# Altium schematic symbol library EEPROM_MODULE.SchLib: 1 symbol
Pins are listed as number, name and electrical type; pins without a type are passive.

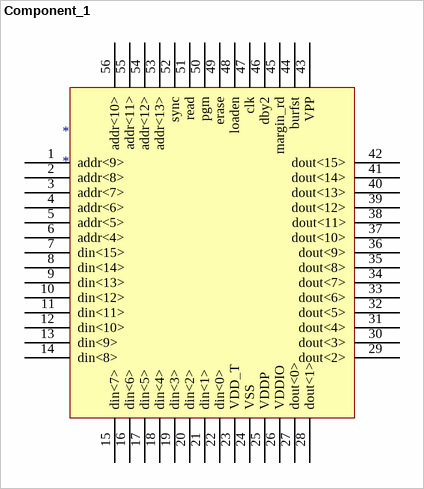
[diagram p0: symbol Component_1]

## Component_1
designator *
pins: 1 addr<9>, 2 addr<8>, 3 addr<7>, 4 addr<6>, 5 addr<5>, 6 addr<4>, 7 din<15>, 8 din<14>, 9 din<13>, 10 din<12>, 11 din<11>, 12 din<10>, 13 din<9>, 14 din<8>, 15 din<7>, 16 din<6>, 17 din<5>, 18 din<4>, 19 din<3>, 20 din<2>, 21 din<1>, 22 din<0>, 23 VDD_T, 24 VSS, 25 VDDP, 26 VDDIO, 27 dout<0>, 28 dout<1>, 29 dout<2>, 30 dout<3>, 31 dout<4>, 32 dout<5>, 33 dout<6>, 34 dout<7>, 35 dout<8>, 36 dout<9>, 37 dout<10>, 38 dout<11>, 39 dout<12>, 40 dout<13>, 41 dout<14>, 42 dout<15>, 43 VPP, 44 burfst, 45 margin_rd, 46 dby2, 47 clk, 48 loaden, 49 erase, 50 pgm, 51 read, 52 sync, 53 addr<13>, 54 addr<12>, 55 addr<11>, 56 addr<10>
